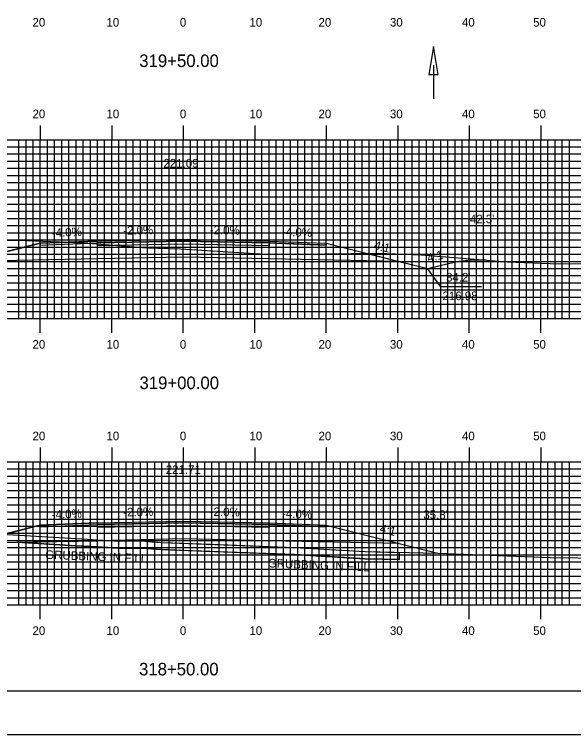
# Model space of a CAD drawing. Extents: x 1820031 to 1820374, y 442591 to 442811.
# Drawn here: x 1820173.1 to 1820251.3, y 442590.5 to 442691.2 of the extents above; entities that cross this region are included whole.
import ezdxf

# ---------------------------------------------------------------- set-up
doc = ezdxf.new("R2010")
doc.units = 0
for name, color, linetype in [('ANNOTATION', 7, 'Continuous'), ('BORDER', 7, 'Continuous'), ('D_Drainage_Ditch_Line', 7, 'Continuous'), ('D_Roadway_Centerline', 7, 'Continuous'), ('D_Roadway_Centerline_Text', 7, 'Continuous'), ('D_Roadway_Edge_Shoulder', 7, 'Continuous'), ('D_Roadway_Edge_TW', 7, 'Continuous'), ('D_Roadway_Pavement', 7, 'Continuous'), ('D_Roadway_SlopeLines', 7, 'Continuous'), ('D_Roadway_SubGrade', 7, 'Continuous'), ('D_Text_Standard', 7, 'Continuous'), ('GRUBBING IN FILL', 7, 'Continuous'), ('H_V ANNOTATION', 7, 'Continuous'), ('MAJOR', 7, 'Continuous'), ('MINOR', 7, 'Continuous'), ('PLOT BOUNDARY', 7, 'Continuous'), ('S_Roadway_Centerline', 7, 'Continuous')]:
    doc.layers.add(name, color=color, linetype=linetype)

msp = doc.modelspace()

# ---------------------------------------------------------------- linework, layer by layer
at = {"layer": 'ANNOTATION'}
msp.add_lwpolyline([(1820238.4, 442653.12), (1820232.71, 442653.12), (1820230.86, 442655.65)], dxfattribs=at)
at = {"layer": 'BORDER'}
msp.add_lwpolyline([(1820047.09, 442596.67), (1820367.09, 442596.67), (1820367.09, 442806.67), (1820047.09, 442806.67)], close=True, dxfattribs=at)
at = {"layer": 'D_Drainage_Ditch_Line'}
msp.add_line((1820231.69, 442684.07), (1820231.69, 442679.37), dxfattribs=at)
msp.add_lwpolyline([(1820231.04, 442682.76), (1820232.35, 442682.76), (1820231.69, 442686.69)], close=True, dxfattribs=at)
at = {"layer": 'D_Roadway_Centerline'}
for points in [[(1820139.04, 442660.93), (1820140.29, 442660.87), (1820141.54, 442660.75), (1820142.79, 442660.54), (1820144.04, 442660.27), (1820162.52, 442655.65), (1820166.52, 442656.65), (1820176.69, 442659.19), (1820184.69, 442659.51), (1820196.69, 442659.75), (1820208.69, 442659.51), (1820216.69, 442659.19), (1820226.86, 442656.65), (1820230.86, 442655.65), (1820233.98, 442656.43), (1820235.23, 442656.69), (1820236.48, 442656.85), (1820237.73, 442656.9), (1820238.98, 442656.86)], [(1820145.48, 442620.05), (1820146.73, 442619.95), (1820147.98, 442619.79), (1820149.23, 442619.56), (1820150.48, 442619.28), (1820162.52, 442616.27), (1820166.52, 442617.27), (1820176.69, 442619.82), (1820184.69, 442620.14), (1820196.69, 442620.38), (1820208.69, 442620.14), (1820216.69, 442619.82), (1820226.86, 442617.27), (1820232.47, 442615.87)]]:
    msp.add_lwpolyline(points, dxfattribs=at)
at = {"layer": 'D_Roadway_Edge_Shoulder'}
for points in [[(1820184.69, 442659.51), (1820176.69, 442659.19), (1820176.69, 442658.94), (1820184.69, 442659.26)], [(1820208.69, 442659.51), (1820216.69, 442659.19), (1820216.69, 442658.94), (1820208.69, 442659.26)], [(1820184.69, 442620.14), (1820176.69, 442619.82), (1820176.69, 442619.57), (1820184.69, 442619.89)], [(1820208.69, 442620.14), (1820216.69, 442619.82), (1820216.69, 442619.57), (1820208.69, 442619.89)]]:
    msp.add_lwpolyline(points, close=True, dxfattribs=at)
at = {"layer": 'D_Roadway_Edge_TW'}
for points in [[(1820184.69, 442659.26), (1820184.69, 442659.51), (1820196.69, 442659.75), (1820208.69, 442659.51), (1820208.69, 442659.26), (1820196.69, 442659.5)], [(1820184.69, 442619.89), (1820184.69, 442620.14), (1820196.69, 442620.38), (1820208.69, 442620.14), (1820208.69, 442619.89), (1820196.69, 442620.13)]]:
    msp.add_lwpolyline(points, close=True, dxfattribs=at)
at = {"layer": 'D_Roadway_Pavement'}
for points in [[(1820184.69, 442658.84), (1820184.69, 442659.26), (1820196.69, 442659.5), (1820208.69, 442659.26), (1820208.69, 442658.84), (1820196.69, 442659.08)], [(1820184.69, 442619.47), (1820184.69, 442619.89), (1820196.69, 442620.13), (1820208.69, 442619.89), (1820208.69, 442619.47), (1820196.69, 442619.71)]]:
    msp.add_lwpolyline(points, close=True, dxfattribs=at)
at = {"layer": 'D_Roadway_SlopeLines'}
for points in [[(1820176.69, 442659.19), (1820162.52, 442655.65)], [(1820216.69, 442659.19), (1820230.86, 442655.65)], [(1820230.86, 442655.65), (1820233.98, 442656.43), (1820235.23, 442656.69), (1820236.48, 442656.85), (1820237.73, 442656.9), (1820238.98, 442656.86)], [(1820176.69, 442619.82), (1820162.52, 442616.27)], [(1820216.69, 442619.82), (1820226.86, 442617.27), (1820232.47, 442615.87)]]:
    msp.add_lwpolyline(points, dxfattribs=at)
at = {"layer": 'D_Roadway_SubGrade'}
for points in [[(1820184.69, 442657.01), (1820166.52, 442656.65), (1820176.69, 442659.19), (1820176.69, 442658.94), (1820184.69, 442659.26), (1820196.69, 442659.5), (1820208.69, 442659.26), (1820216.69, 442658.94), (1820216.69, 442659.19), (1820226.86, 442656.65), (1820208.69, 442657.01), (1820196.69, 442657.25)], [(1820184.69, 442617.64), (1820166.52, 442617.27), (1820176.69, 442619.82), (1820176.69, 442619.57), (1820184.69, 442619.89), (1820196.69, 442620.13), (1820208.69, 442619.89), (1820216.69, 442619.57), (1820216.69, 442619.82), (1820226.86, 442617.27), (1820208.69, 442617.64), (1820196.69, 442617.88)]]:
    msp.add_lwpolyline(points, close=True, dxfattribs=at)
at = {"layer": 'GRUBBING IN FILL'}
msp.add_line((1820226.86, 442616.01), (1820226.86, 442615.01), dxfattribs=at)
msp.add_line((1820226.86, 442616.01), (1820226.86, 442615.01), dxfattribs=at)
for points in [[(1820173.44, 442617.41), (1820184.69, 442617.64), (1820186.3, 442617.67), (1820187.05, 442617.63), (1820187.68, 442617.59), (1820189.27, 442617.6), (1820189.27, 442617.6), (1820190.87, 442617.6), (1820192.28, 442617.5), (1820193.69, 442617.4), (1820196.69, 442617.29), (1820196.69, 442616.29), (1820193.63, 442616.4), (1820190.84, 442616.6), (1820189.25, 442616.6), (1820187.65, 442616.59), (1820184.66, 442616.76), (1820181.67, 442616.93)], [(1820173.44, 442617.41), (1820184.69, 442617.64), (1820186.3, 442617.67), (1820187.05, 442617.63), (1820187.68, 442617.59), (1820189.27, 442617.6), (1820189.27, 442617.6), (1820190.87, 442617.6), (1820192.28, 442617.5), (1820193.69, 442617.4), (1820196.69, 442617.29), (1820196.69, 442616.29), (1820193.63, 442616.4), (1820190.84, 442616.6), (1820189.25, 442616.6), (1820187.65, 442616.59), (1820184.66, 442616.76), (1820181.67, 442616.93)], [(1820196.69, 442617.29), (1820202.97, 442617.05), (1820212.26, 442616.7), (1820217.19, 442616.41), (1820222.13, 442616.12), (1820226.86, 442616.01), (1820226.86, 442615.01), (1820224.48, 442615.07), (1820222.09, 442615.12), (1820217.15, 442615.41), (1820212.21, 442615.7), (1820202.92, 442616.05), (1820196.69, 442616.29)], [(1820196.69, 442617.29), (1820202.97, 442617.05), (1820212.26, 442616.7), (1820217.19, 442616.41), (1820222.13, 442616.12), (1820226.86, 442616.01), (1820226.86, 442615.01), (1820224.48, 442615.07), (1820222.09, 442615.12), (1820217.15, 442615.41), (1820212.21, 442615.7), (1820202.92, 442616.05), (1820196.69, 442616.29)]]:
    msp.add_lwpolyline(points, close=True, dxfattribs=at)
msp.add_lwpolyline([(1820173.44, 442617.41), (1820181.67, 442616.93), (1820187.65, 442616.59), (1820190.84, 442616.6), (1820193.63, 442616.4), (1820212.21, 442615.7), (1820222.09, 442615.12), (1820226.86, 442615.01)], dxfattribs=at)
msp.add_lwpolyline([(1820173.44, 442617.41), (1820181.67, 442616.93), (1820187.65, 442616.59), (1820190.84, 442616.6), (1820193.63, 442616.4), (1820212.21, 442615.7), (1820222.09, 442615.12), (1820226.86, 442615.01)], dxfattribs=at)
at = {"layer": 'MAJOR'}
for p, q in [((1820176.69, 442675.67), (1820176.69, 442673.67)), ((1820186.69, 442675.67), (1820186.69, 442673.67)), ((1820196.69, 442675.67), (1820196.69, 442673.67)), ((1820206.69, 442675.67), (1820206.69, 442673.67)), ((1820216.69, 442675.67), (1820216.69, 442673.67)), ((1820226.69, 442675.67), (1820226.69, 442673.67)), ((1820236.69, 442675.67), (1820236.69, 442673.67)), ((1820246.69, 442675.67), (1820246.69, 442673.67)), ((1820056.69, 442673.67), (1820336.69, 442673.67)), ((1820056.69, 442673.67), (1820336.69, 442673.67)), ((1820176.69, 442648.67), (1820176.69, 442673.67)), ((1820186.69, 442648.67), (1820186.69, 442673.67)), ((1820196.69, 442648.67), (1820196.69, 442673.67)), ((1820206.69, 442648.67), (1820206.69, 442673.67)), ((1820216.69, 442648.67), (1820216.69, 442673.67)), ((1820226.69, 442648.67), (1820226.69, 442673.67)), ((1820236.69, 442648.67), (1820236.69, 442673.67)), ((1820246.69, 442648.67), (1820246.69, 442673.67)), ((1820056.69, 442668.67), (1820336.69, 442668.67)), ((1820056.69, 442663.67), (1820336.69, 442663.67)), ((1820056.69, 442658.67), (1820336.69, 442658.67)), ((1820056.69, 442653.67), (1820336.69, 442653.67)), ((1820056.69, 442648.67), (1820336.69, 442648.67)), ((1820056.69, 442648.67), (1820336.69, 442648.67)), ((1820176.69, 442646.66), (1820176.69, 442648.67)), ((1820186.69, 442646.66), (1820186.69, 442648.67)), ((1820196.69, 442646.66), (1820196.69, 442648.67)), ((1820206.69, 442646.66), (1820206.69, 442648.67)), ((1820216.69, 442646.66), (1820216.69, 442648.67)), ((1820226.69, 442646.66), (1820226.69, 442648.67)), ((1820236.69, 442646.66), (1820236.69, 442648.67)), ((1820246.69, 442646.66), (1820246.69, 442648.67)), ((1820176.69, 442630.67), (1820176.69, 442628.67)), ((1820186.69, 442630.67), (1820186.69, 442628.67)), ((1820196.69, 442630.67), (1820196.69, 442628.67)), ((1820206.69, 442630.67), (1820206.69, 442628.67)), ((1820216.69, 442630.67), (1820216.69, 442628.67)), ((1820226.69, 442630.67), (1820226.69, 442628.67)), ((1820236.69, 442630.67), (1820236.69, 442628.67)), ((1820246.69, 442630.67), (1820246.69, 442628.67)), ((1820056.69, 442628.67), (1820336.69, 442628.67)), ((1820056.69, 442628.67), (1820336.69, 442628.67)), ((1820176.69, 442608.67), (1820176.69, 442628.67)), ((1820186.69, 442608.67), (1820186.69, 442628.67)), ((1820196.69, 442608.67), (1820196.69, 442628.67)), ((1820206.69, 442608.67), (1820206.69, 442628.67)), ((1820216.69, 442608.67), (1820216.69, 442628.67)), ((1820226.69, 442608.67), (1820226.69, 442628.67)), ((1820236.69, 442608.67), (1820236.69, 442628.67)), ((1820246.69, 442608.67), (1820246.69, 442628.67)), ((1820056.69, 442623.67), (1820336.69, 442623.67)), ((1820056.69, 442618.67), (1820336.69, 442618.67)), ((1820056.69, 442613.67), (1820336.69, 442613.67)), ((1820056.69, 442608.67), (1820336.69, 442608.67)), ((1820056.69, 442608.67), (1820336.69, 442608.67)), ((1820176.69, 442606.66), (1820176.69, 442608.67)), ((1820186.69, 442606.66), (1820186.69, 442608.67)), ((1820196.69, 442606.66), (1820196.69, 442608.67)), ((1820206.69, 442606.66), (1820206.69, 442608.67)), ((1820216.69, 442606.66), (1820216.69, 442608.67)), ((1820226.69, 442606.66), (1820226.69, 442608.67)), ((1820236.69, 442606.66), (1820236.69, 442608.67)), ((1820246.69, 442606.66), (1820246.69, 442608.67))]:
    msp.add_line(p, q, dxfattribs=at)
at = {"layer": 'MINOR'}
for p, q in [((1820173.69, 442648.67), (1820173.69, 442673.67)), ((1820174.69, 442648.67), (1820174.69, 442673.67)), ((1820175.69, 442648.67), (1820175.69, 442673.67)), ((1820177.69, 442648.67), (1820177.69, 442673.67)), ((1820178.69, 442648.67), (1820178.69, 442673.67)), ((1820179.69, 442648.67), (1820179.69, 442673.67)), ((1820180.69, 442648.67), (1820180.69, 442673.67)), ((1820181.69, 442648.67), (1820181.69, 442673.67)), ((1820182.69, 442648.67), (1820182.69, 442673.67)), ((1820183.69, 442648.67), (1820183.69, 442673.67)), ((1820184.69, 442648.67), (1820184.69, 442673.67)), ((1820185.69, 442648.67), (1820185.69, 442673.67)), ((1820187.69, 442648.67), (1820187.69, 442673.67)), ((1820188.69, 442648.67), (1820188.69, 442673.67)), ((1820189.69, 442648.67), (1820189.69, 442673.67)), ((1820190.69, 442648.67), (1820190.69, 442673.67)), ((1820191.69, 442648.67), (1820191.69, 442673.67)), ((1820192.69, 442648.67), (1820192.69, 442673.67)), ((1820193.69, 442648.67), (1820193.69, 442673.67)), ((1820194.69, 442648.67), (1820194.69, 442673.67)), ((1820195.69, 442648.67), (1820195.69, 442673.67)), ((1820197.69, 442648.67), (1820197.69, 442673.67)), ((1820198.69, 442648.67), (1820198.69, 442673.67)), ((1820199.69, 442648.67), (1820199.69, 442673.67)), ((1820200.69, 442648.67), (1820200.69, 442673.67)), ((1820201.69, 442648.67), (1820201.69, 442673.67)), ((1820202.69, 442648.67), (1820202.69, 442673.67)), ((1820203.69, 442648.67), (1820203.69, 442673.67)), ((1820204.69, 442648.67), (1820204.69, 442673.67)), ((1820205.69, 442648.67), (1820205.69, 442673.67)), ((1820207.69, 442648.67), (1820207.69, 442673.67)), ((1820208.69, 442648.67), (1820208.69, 442673.67)), ((1820209.69, 442648.67), (1820209.69, 442673.67)), ((1820210.69, 442648.67), (1820210.69, 442673.67)), ((1820211.69, 442648.67), (1820211.69, 442673.67)), ((1820212.69, 442648.67), (1820212.69, 442673.67)), ((1820213.69, 442648.67), (1820213.69, 442673.67)), ((1820214.69, 442648.67), (1820214.69, 442673.67)), ((1820215.69, 442648.67), (1820215.69, 442673.67)), ((1820217.69, 442648.67), (1820217.69, 442673.67)), ((1820218.69, 442648.67), (1820218.69, 442673.67)), ((1820219.69, 442648.67), (1820219.69, 442673.67)), ((1820220.69, 442648.67), (1820220.69, 442673.67)), ((1820221.69, 442648.67), (1820221.69, 442673.67)), ((1820222.69, 442648.67), (1820222.69, 442673.67)), ((1820223.69, 442648.67), (1820223.69, 442673.67)), ((1820224.69, 442648.67), (1820224.69, 442673.67)), ((1820225.69, 442648.67), (1820225.69, 442673.67)), ((1820227.69, 442648.67), (1820227.69, 442673.67)), ((1820228.69, 442648.67), (1820228.69, 442673.67)), ((1820229.69, 442648.67), (1820229.69, 442673.67)), ((1820230.69, 442648.67), (1820230.69, 442673.67)), ((1820231.69, 442648.67), (1820231.69, 442673.67)), ((1820232.69, 442648.67), (1820232.69, 442673.67)), ((1820233.69, 442648.67), (1820233.69, 442673.67)), ((1820234.69, 442648.67), (1820234.69, 442673.67)), ((1820235.69, 442648.67), (1820235.69, 442673.67)), ((1820237.69, 442648.67), (1820237.69, 442673.67)), ((1820238.69, 442648.67), (1820238.69, 442673.67)), ((1820239.69, 442648.67), (1820239.69, 442673.67)), ((1820240.69, 442648.67), (1820240.69, 442673.67)), ((1820241.69, 442648.67), (1820241.69, 442673.67)), ((1820242.69, 442648.67), (1820242.69, 442673.67)), ((1820243.69, 442648.67), (1820243.69, 442673.67)), ((1820244.69, 442648.67), (1820244.69, 442673.67)), ((1820245.69, 442648.67), (1820245.69, 442673.67)), ((1820247.69, 442648.67), (1820247.69, 442673.67)), ((1820248.69, 442648.67), (1820248.69, 442673.67)), ((1820249.69, 442648.67), (1820249.69, 442673.67)), ((1820250.69, 442648.67), (1820250.69, 442673.67)), ((1820056.69, 442672.67), (1820336.69, 442672.67)), ((1820056.69, 442671.67), (1820336.69, 442671.67)), ((1820056.69, 442670.67), (1820336.69, 442670.67)), ((1820056.69, 442669.67), (1820336.69, 442669.67)), ((1820056.69, 442667.67), (1820336.69, 442667.67)), ((1820056.69, 442666.67), (1820336.69, 442666.67)), ((1820056.69, 442665.67), (1820336.69, 442665.67)), ((1820056.69, 442664.67), (1820336.69, 442664.67)), ((1820056.69, 442662.67), (1820336.69, 442662.67)), ((1820056.69, 442661.67), (1820336.69, 442661.67)), ((1820056.69, 442660.67), (1820336.69, 442660.67)), ((1820056.69, 442659.67), (1820336.69, 442659.67)), ((1820056.69, 442657.67), (1820336.69, 442657.67)), ((1820056.69, 442656.67), (1820336.69, 442656.67)), ((1820056.69, 442655.67), (1820336.69, 442655.67)), ((1820056.69, 442654.67), (1820336.69, 442654.67)), ((1820056.69, 442652.67), (1820336.69, 442652.67)), ((1820056.69, 442651.67), (1820336.69, 442651.67)), ((1820056.69, 442650.67), (1820336.69, 442650.67)), ((1820056.69, 442649.67), (1820336.69, 442649.67)), ((1820173.69, 442608.67), (1820173.69, 442628.67)), ((1820174.69, 442608.67), (1820174.69, 442628.67)), ((1820175.69, 442608.67), (1820175.69, 442628.67)), ((1820177.69, 442608.67), (1820177.69, 442628.67)), ((1820178.69, 442608.67), (1820178.69, 442628.67)), ((1820179.69, 442608.67), (1820179.69, 442628.67)), ((1820180.69, 442608.67), (1820180.69, 442628.67)), ((1820181.69, 442608.67), (1820181.69, 442628.67)), ((1820182.69, 442608.67), (1820182.69, 442628.67)), ((1820183.69, 442608.67), (1820183.69, 442628.67)), ((1820184.69, 442608.67), (1820184.69, 442628.67)), ((1820185.69, 442608.67), (1820185.69, 442628.67)), ((1820187.69, 442608.67), (1820187.69, 442628.67)), ((1820188.69, 442608.67), (1820188.69, 442628.67)), ((1820189.69, 442608.67), (1820189.69, 442628.67)), ((1820190.69, 442608.67), (1820190.69, 442628.67)), ((1820191.69, 442608.67), (1820191.69, 442628.67)), ((1820192.69, 442608.67), (1820192.69, 442628.67)), ((1820193.69, 442608.67), (1820193.69, 442628.67)), ((1820194.69, 442608.67), (1820194.69, 442628.67)), ((1820195.69, 442608.67), (1820195.69, 442628.67)), ((1820197.69, 442608.67), (1820197.69, 442628.67)), ((1820198.69, 442608.67), (1820198.69, 442628.67)), ((1820199.69, 442608.67), (1820199.69, 442628.67)), ((1820200.69, 442608.67), (1820200.69, 442628.67)), ((1820201.69, 442608.67), (1820201.69, 442628.67)), ((1820202.69, 442608.67), (1820202.69, 442628.67)), ((1820203.69, 442608.67), (1820203.69, 442628.67)), ((1820204.69, 442608.67), (1820204.69, 442628.67)), ((1820205.69, 442608.67), (1820205.69, 442628.67)), ((1820207.69, 442608.67), (1820207.69, 442628.67)), ((1820208.69, 442608.67), (1820208.69, 442628.67)), ((1820209.69, 442608.67), (1820209.69, 442628.67)), ((1820210.69, 442608.67), (1820210.69, 442628.67)), ((1820211.69, 442608.67), (1820211.69, 442628.67)), ((1820212.69, 442608.67), (1820212.69, 442628.67)), ((1820213.69, 442608.67), (1820213.69, 442628.67)), ((1820214.69, 442608.67), (1820214.69, 442628.67)), ((1820215.69, 442608.67), (1820215.69, 442628.67)), ((1820217.69, 442608.67), (1820217.69, 442628.67)), ((1820218.69, 442608.67), (1820218.69, 442628.67)), ((1820219.69, 442608.67), (1820219.69, 442628.67)), ((1820220.69, 442608.67), (1820220.69, 442628.67)), ((1820221.69, 442608.67), (1820221.69, 442628.67)), ((1820222.69, 442608.67), (1820222.69, 442628.67)), ((1820223.69, 442608.67), (1820223.69, 442628.67)), ((1820224.69, 442608.67), (1820224.69, 442628.67)), ((1820225.69, 442608.67), (1820225.69, 442628.67)), ((1820227.69, 442608.67), (1820227.69, 442628.67)), ((1820228.69, 442608.67), (1820228.69, 442628.67)), ((1820229.69, 442608.67), (1820229.69, 442628.67)), ((1820230.69, 442608.67), (1820230.69, 442628.67)), ((1820231.69, 442608.67), (1820231.69, 442628.67)), ((1820232.69, 442608.67), (1820232.69, 442628.67)), ((1820233.69, 442608.67), (1820233.69, 442628.67)), ((1820234.69, 442608.67), (1820234.69, 442628.67)), ((1820235.69, 442608.67), (1820235.69, 442628.67)), ((1820237.69, 442608.67), (1820237.69, 442628.67)), ((1820238.69, 442608.67), (1820238.69, 442628.67)), ((1820239.69, 442608.67), (1820239.69, 442628.67)), ((1820240.69, 442608.67), (1820240.69, 442628.67)), ((1820241.69, 442608.67), (1820241.69, 442628.67)), ((1820242.69, 442608.67), (1820242.69, 442628.67)), ((1820243.69, 442608.67), (1820243.69, 442628.67)), ((1820244.69, 442608.67), (1820244.69, 442628.67)), ((1820245.69, 442608.67), (1820245.69, 442628.67)), ((1820247.69, 442608.67), (1820247.69, 442628.67)), ((1820248.69, 442608.67), (1820248.69, 442628.67)), ((1820249.69, 442608.67), (1820249.69, 442628.67)), ((1820250.69, 442608.67), (1820250.69, 442628.67)), ((1820056.69, 442627.67), (1820336.69, 442627.67)), ((1820056.69, 442626.67), (1820336.69, 442626.67)), ((1820056.69, 442625.67), (1820336.69, 442625.67)), ((1820056.69, 442624.67), (1820336.69, 442624.67)), ((1820056.69, 442622.67), (1820336.69, 442622.67)), ((1820056.69, 442621.67), (1820336.69, 442621.67)), ((1820056.69, 442620.67), (1820336.69, 442620.67)), ((1820056.69, 442619.67), (1820336.69, 442619.67)), ((1820056.69, 442617.67), (1820336.69, 442617.67)), ((1820056.69, 442616.67), (1820336.69, 442616.67)), ((1820056.69, 442615.67), (1820336.69, 442615.67)), ((1820056.69, 442614.67), (1820336.69, 442614.67)), ((1820056.69, 442612.67), (1820336.69, 442612.67)), ((1820056.69, 442611.67), (1820336.69, 442611.67)), ((1820056.69, 442610.67), (1820336.69, 442610.67)), ((1820056.69, 442609.67), (1820336.69, 442609.67))]:
    msp.add_line(p, q, dxfattribs=at)
at = {"layer": 'PLOT BOUNDARY'}
msp.add_lwpolyline([(1820030.9, 442590.55), (1820370.9, 442590.55), (1820370.9, 442810.55), (1820030.9, 442810.55)], close=True, dxfattribs=at)
at = {"layer": 'S_Roadway_Centerline'}
for points in [[(1820056.69, 442664.03), (1820057, 442664.03), (1820063.6, 442662.91), (1820081.74, 442662.45), (1820101.72, 442662.02), (1820110.61, 442661.61), (1820124.72, 442660.91), (1820130.07, 442660.88), (1820140.73, 442660.94), (1820148.98, 442660.46), (1820155.71, 442660.07), (1820160.35, 442659.82), (1820174.75, 442659.57), (1820182.84, 442659.24), (1820191.56, 442658.58), (1820196.32, 442658.43), (1820208.93, 442657.64), (1820224, 442657.83), (1820229.94, 442657.56), (1820241.99, 442656.62), (1820249.22, 442656.31), (1820259.82, 442656.42)], [(1820056.69, 442622.61), (1820064.68, 442621.85), (1820076.04, 442621.85), (1820086.41, 442621.89), (1820099.23, 442621.29), (1820102.31, 442621.14), (1820107.46, 442621.06), (1820119.88, 442620.93), (1820126.83, 442620.76), (1820136.4, 442620.57), (1820138.18, 442620.48), (1820181.73, 442617.93), (1820187.68, 442617.59), (1820190.87, 442617.6), (1820193.69, 442617.4), (1820212.26, 442616.7), (1820222.13, 442616.12), (1820232.29, 442615.88), (1820248.06, 442615.29), (1820255.72, 442615.2)]]:
    msp.add_lwpolyline(points, dxfattribs=at)

# ---------------------------------------------------------------- texts
at = {"layer": 'ANNOTATION'}
for s, rotation, p in [('-2.0%', 1.1458, (1820188.3, 442660.38)), ('-2.0%', 358.8542, (1820200.38, 442660.48)), ('-4.0%', 2.2906, (1820178.32, 442660.06)), ('-4.0%', 357.7094, (1820210.48, 442660.24)), ('4:1', 345.9638, (1820223.28, 442658.41)), ('4:1', 14.0362, (1820230.96, 442656.53)), ('-2.0%', 1.1458, (1820188.3, 442621.01)), ('-2.0%', 358.8542, (1820200.38, 442621.1)), ('-4.0%', 2.2906, (1820178.32, 442620.68)), ('-4.0%', 357.7094, (1820210.48, 442620.87)), ('4:1', 345.9638, (1820224.08, 442618.83))]:
    msp.add_text(s, height=1.2, rotation=rotation, dxfattribs=at).set_placement(p)
for s, p in [("34.2'", (1820233.44, 442653.85)), ('216.98', (1820232.94, 442651.25))]:
    msp.add_text(s, height=1.2, dxfattribs=at).set_placement(p)
at = {"layer": 'D_Roadway_Centerline'}
for s, p in [('C', (1820196.69, 442659.75)), ('L', (1820196.69, 442659.74)), ('C', (1820196.69, 442620.38)), ('L', (1820196.69, 442620.37))]:
    msp.add_text(s, height=0.0146, dxfattribs=at).set_placement(p)
at = {"layer": 'D_Roadway_Centerline_Text'}
for s, p in [('221.09', (1820193.91, 442669.78)), ('221.71', (1820194.24, 442626.97))]:
    msp.add_text(s, height=1.2, dxfattribs=at).set_placement(p)
at = {"layer": 'D_Text_Standard'}
for s, p in [("42.3'", (1820236.77, 442661.99)), ("35.8'", (1820230.26, 442620.67))]:
    msp.add_text(s, height=1.2, dxfattribs=at).set_placement(p)
at = {"layer": 'GRUBBING IN FILL'}
for p in [(1820177.36, 442615.12), (1820208.49, 442613.92)]:
    msp.add_text('GRUBBING IN FILL', height=1.2, rotation=357.668, dxfattribs=at).set_placement(p)
at = {"layer": 'H_V ANNOTATION'}
for s, height, p in [('20', 1.2, (1820175.6, 442689.47)), ('10', 1.2, (1820185.94, 442689.47)), ('0', 1.2, (1820196.21, 442689.47)), ('10', 1.2, (1820205.94, 442689.47)), ('20', 1.2, (1820215.6, 442689.47)), ('30', 1.2, (1820225.59, 442689.47)), ('40', 1.2, (1820235.66, 442689.47)), ('50', 1.2, (1820245.62, 442689.47)), ('319+50.00', 1.75, (1820190.53, 442683.82)), ('20', 1.2, (1820175.6, 442676.67)), ('10', 1.2, (1820185.94, 442676.67)), ('0', 1.2, (1820196.21, 442676.67)), ('10', 1.2, (1820205.94, 442676.67)), ('20', 1.2, (1820215.6, 442676.67)), ('30', 1.2, (1820225.59, 442676.67)), ('40', 1.2, (1820235.66, 442676.67)), ('50', 1.2, (1820245.62, 442676.67)), ('20', 1.2, (1820175.6, 442644.47)), ('10', 1.2, (1820185.94, 442644.47)), ('0', 1.2, (1820196.21, 442644.47)), ('10', 1.2, (1820205.94, 442644.47)), ('20', 1.2, (1820215.6, 442644.47)), ('30', 1.2, (1820225.59, 442644.47)), ('40', 1.2, (1820235.66, 442644.47)), ('50', 1.2, (1820245.62, 442644.47)), ('319+00.00', 1.75, (1820190.56, 442638.82)), ('20', 1.2, (1820175.6, 442631.67)), ('10', 1.2, (1820185.94, 442631.67)), ('0', 1.2, (1820196.21, 442631.67)), ('10', 1.2, (1820205.94, 442631.67)), ('20', 1.2, (1820215.6, 442631.67)), ('30', 1.2, (1820225.59, 442631.67)), ('40', 1.2, (1820235.66, 442631.67)), ('50', 1.2, (1820245.62, 442631.67)), ('20', 1.2, (1820175.6, 442604.47)), ('10', 1.2, (1820185.94, 442604.47)), ('0', 1.2, (1820196.21, 442604.47)), ('10', 1.2, (1820205.94, 442604.47)), ('20', 1.2, (1820215.6, 442604.47)), ('30', 1.2, (1820225.59, 442604.47)), ('40', 1.2, (1820235.66, 442604.47)), ('50', 1.2, (1820245.62, 442604.47)), ('318+50.00', 1.75, (1820190.5, 442598.82))]:
    msp.add_text(s, height=height, dxfattribs=at).set_placement(p)

doc.saveas('drawing.dxf')
